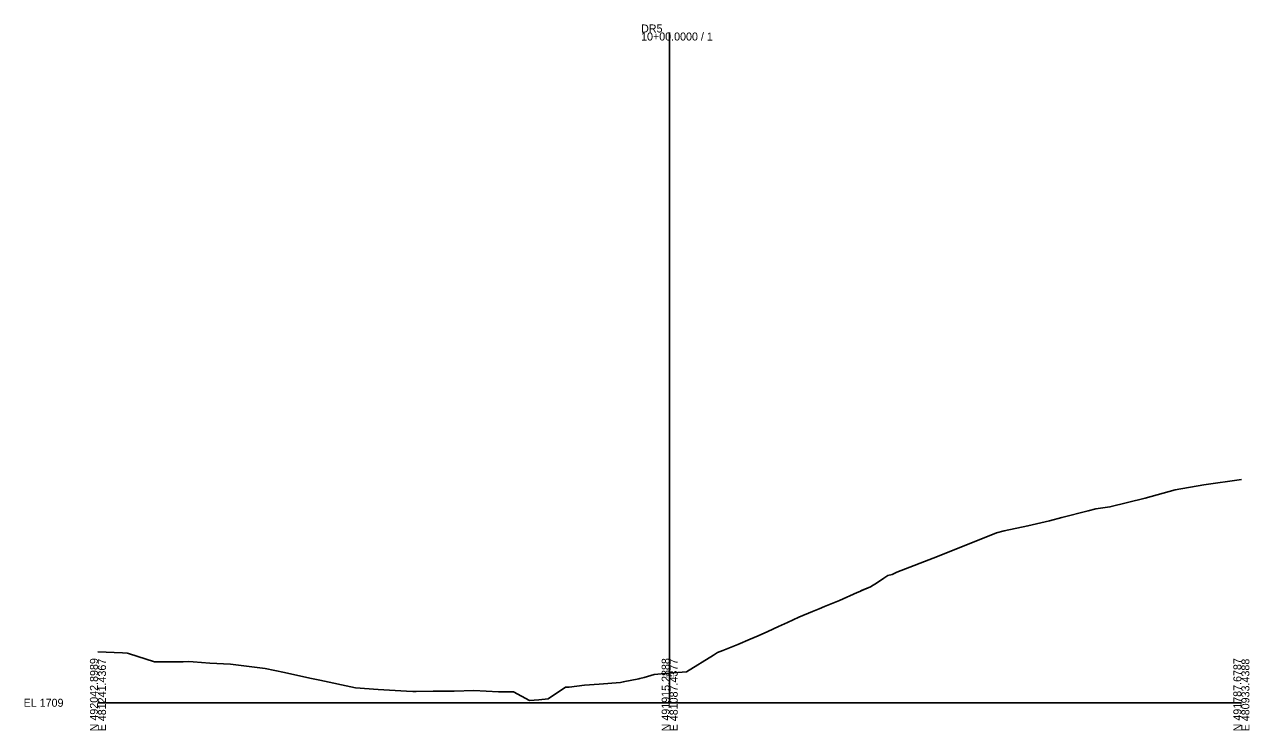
# Model space of a CAD drawing. Extents: x -26 to 403, y -10 to 2534.
# Drawn here: x -25.7 to 402.8, y -9.7 to 237.1 of the extents above; entities that cross this region are included whole.
import ezdxf

# ---------------------------------------------------------------- set-up
doc = ezdxf.new("R2010")
doc.units = 0
for name, color, linetype in [('Exist Cross Section Cell', 7, 'Continuous'), ('Exist XS Center Line Elevation Label', 7, 'Continuous'), ('Exist XS Ground Line', 7, 'Continuous'), ('Scratch_Level_5', 7, 'Continuous')]:
    doc.layers.add(name, color=color, linetype=linetype)

msp = doc.modelspace()

# ---------------------------------------------------------------- linework, layer by layer
at = {"layer": 'Exist Cross Section Cell'}
for p, q in [((200, 0), (200, 234.35)), ((0, 0), (200, 0)), ((200, 0), (400, 0))]:
    msp.add_line(p, q, dxfattribs=at)
at = {"layer": 'Exist XS Ground Line'}
msp.add_lwpolyline([(0, 17.78), (8.54, 17.43), (10.25, 17.36), (10.73, 17.19), (19.8, 14.29), (29.79, 14.35), (31.83, 14.38), (33.35, 14.29), (39.17, 13.82), (46.34, 13.51), (58.52, 11.95), (65.23, 10.58), (74.17, 8.55), (75.82, 8.22), (77.58, 7.86), (90.06, 5.24), (98.01, 4.63), (107.92, 4.09), (110.2, 3.94), (111.29, 3.95), (117.31, 4.09), (124.57, 4.09), (131.51, 4.33), (140.16, 3.84), (145.34, 3.85), (150.98, 0.77), (154.26, 0.97), (157.53, 1.42), (163.59, 5.48), (164.8, 5.48), (170.24, 6.14), (175.3, 6.55), (182.75, 7.09), (183.78, 7.29), (189.22, 8.37), (189.6, 8.47), (191.04, 8.85), (194.57, 9.86), (198.35, 10.24), (200, 10.37), (205.88, 10.81), (215.37, 16.7), (216.75, 17.54), (218.62, 18.29), (223.86, 20.37), (228.19, 22.22), (230.96, 23.36), (234.3, 24.91), (238.06, 26.64), (241.18, 28.03), (245.17, 29.88), (249.98, 31.92), (252.27, 32.86), (254.17, 33.66), (259.38, 35.81), (265.65, 38.58), (266.48, 38.94), (267.2, 39.26), (270.23, 40.53), (272.66, 42.07), (274.94, 43.51), (276.33, 44.49), (277.86, 44.86), (279.52, 45.67), (293.73, 51.18), (314.36, 59.43), (316.99, 60.08), (325.32, 61.84), (332.82, 63.65), (337.16, 64.76), (346.4, 67.05), (349.12, 67.82), (354.01, 68.47), (366.37, 71.54), (376.87, 74.44), (386.9, 76.14), (400, 78.12)], dxfattribs=at)
at = {"layer": 'Scratch_Level_5'}
msp.add_lwpolyline([(0, 17.78), (8.54, 17.43), (10.25, 17.36), (10.73, 17.19), (19.8, 14.29), (29.79, 14.35), (31.83, 14.38), (33.35, 14.29), (39.17, 13.82), (46.34, 13.51), (58.52, 11.95), (65.23, 10.58), (74.17, 8.55), (75.82, 8.22), (77.58, 7.86), (90.06, 5.24), (98.01, 4.63), (107.92, 4.09), (110.2, 3.94), (111.29, 3.95), (117.31, 4.09), (124.57, 4.09), (131.51, 4.33), (140.16, 3.84), (145.34, 3.85), (150.98, 0.77), (154.26, 0.97), (157.53, 1.42), (163.59, 5.48), (164.8, 5.48), (170.24, 6.14), (175.3, 6.55), (182.75, 7.09), (183.78, 7.29), (189.22, 8.37), (189.6, 8.47), (191.04, 8.85), (194.57, 9.86), (198.35, 10.24), (200, 10.37), (205.88, 10.81), (215.37, 16.7), (216.75, 17.54), (218.62, 18.29), (223.86, 20.37), (228.19, 22.22), (230.96, 23.36), (234.3, 24.91), (238.06, 26.64), (241.18, 28.03), (245.17, 29.88), (249.98, 31.92), (252.27, 32.86), (254.17, 33.66), (259.38, 35.81), (265.65, 38.58), (266.48, 38.94), (267.16, 39.24), (270.23, 40.53)], dxfattribs=at)

# ---------------------------------------------------------------- texts
at = {"layer": 'Exist Cross Section Cell'}
for s, p in [('DR5', (190, 234.35)), ('10+00.0000 / 1', (190, 231.55)), ('EL 1709', (-26, -1.4))]:
    msp.add_text(s, height=2.8, dxfattribs=at).set_placement(p)
for s, p in [('N 492042.8989', (0, -10)), ('E 481241.4367', (2.8, -10)), ('N 491915.2888', (200, -10)), ('E 481087.4377', (202.8, -10)), ('N 491787.6787', (400, -10)), ('E 480933.4388', (402.8, -10))]:
    msp.add_text(s, height=2.8, rotation=90, dxfattribs=at).set_placement(p)
at = {"layer": 'Exist XS Center Line Elevation Label'}
msp.add_text('1719.37', height=0.75, dxfattribs=at).set_placement((198.44, 8.79))

doc.saveas('drawing.dxf')
